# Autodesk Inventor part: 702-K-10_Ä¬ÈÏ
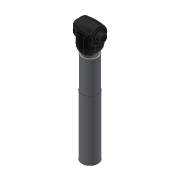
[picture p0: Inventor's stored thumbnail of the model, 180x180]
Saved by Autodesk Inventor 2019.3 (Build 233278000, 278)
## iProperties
Created: 2010-06
Part Number: 702-K-10_Ä¬ÈÏ
Material: Ogólny
Document SubType Name: Modeling
Designer: CADENGINEERING4
Density: 1 g/cm^3
Appearance: Domyślna
Author: CADENGINEERING4
Revision Number: ÈÎºÎ
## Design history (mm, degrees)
feature "NONE"
feature "NONE:1"
node "Bryła1"
node "Bryła2"
